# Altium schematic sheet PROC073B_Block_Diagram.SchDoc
size 431 x 279 mm; Date: Not shown in title block; ApprovedBy: Not shown in title block; CheckedBy: Not shown in title block; Author: Not shown in title block; CompanyName: Not shown in title block; Engineer: Not shown in title block; Organization: Not shown in title block; Address1: Not shown in title block; Address2: Not shown in title block; Address3: Not shown in title block; Address4: Not shown in title block; DocumentNumber: 1; Revision: Use project parameter SCH_Rev; SheetNumber: 1; SheetTotal: 9; PageSetup: Record=PageOptions¦CenterHorizontal=True¦CenterVertical=True¦PrintScale=1.00¦XCorrection=1.00¦YCorrection=1.00¦PrintKind=0¦BorderSize=5000000¦LeftOffset=0¦BottomOffset=0¦Orientation=2¦PaperLength=1000¦PaperWidth=1000¦Scale=100¦PaperSource=15¦PrintQuality=600¦MediaType=1¦DitherType=10¦PaperKind=Letter¦PrintScaleMode=1
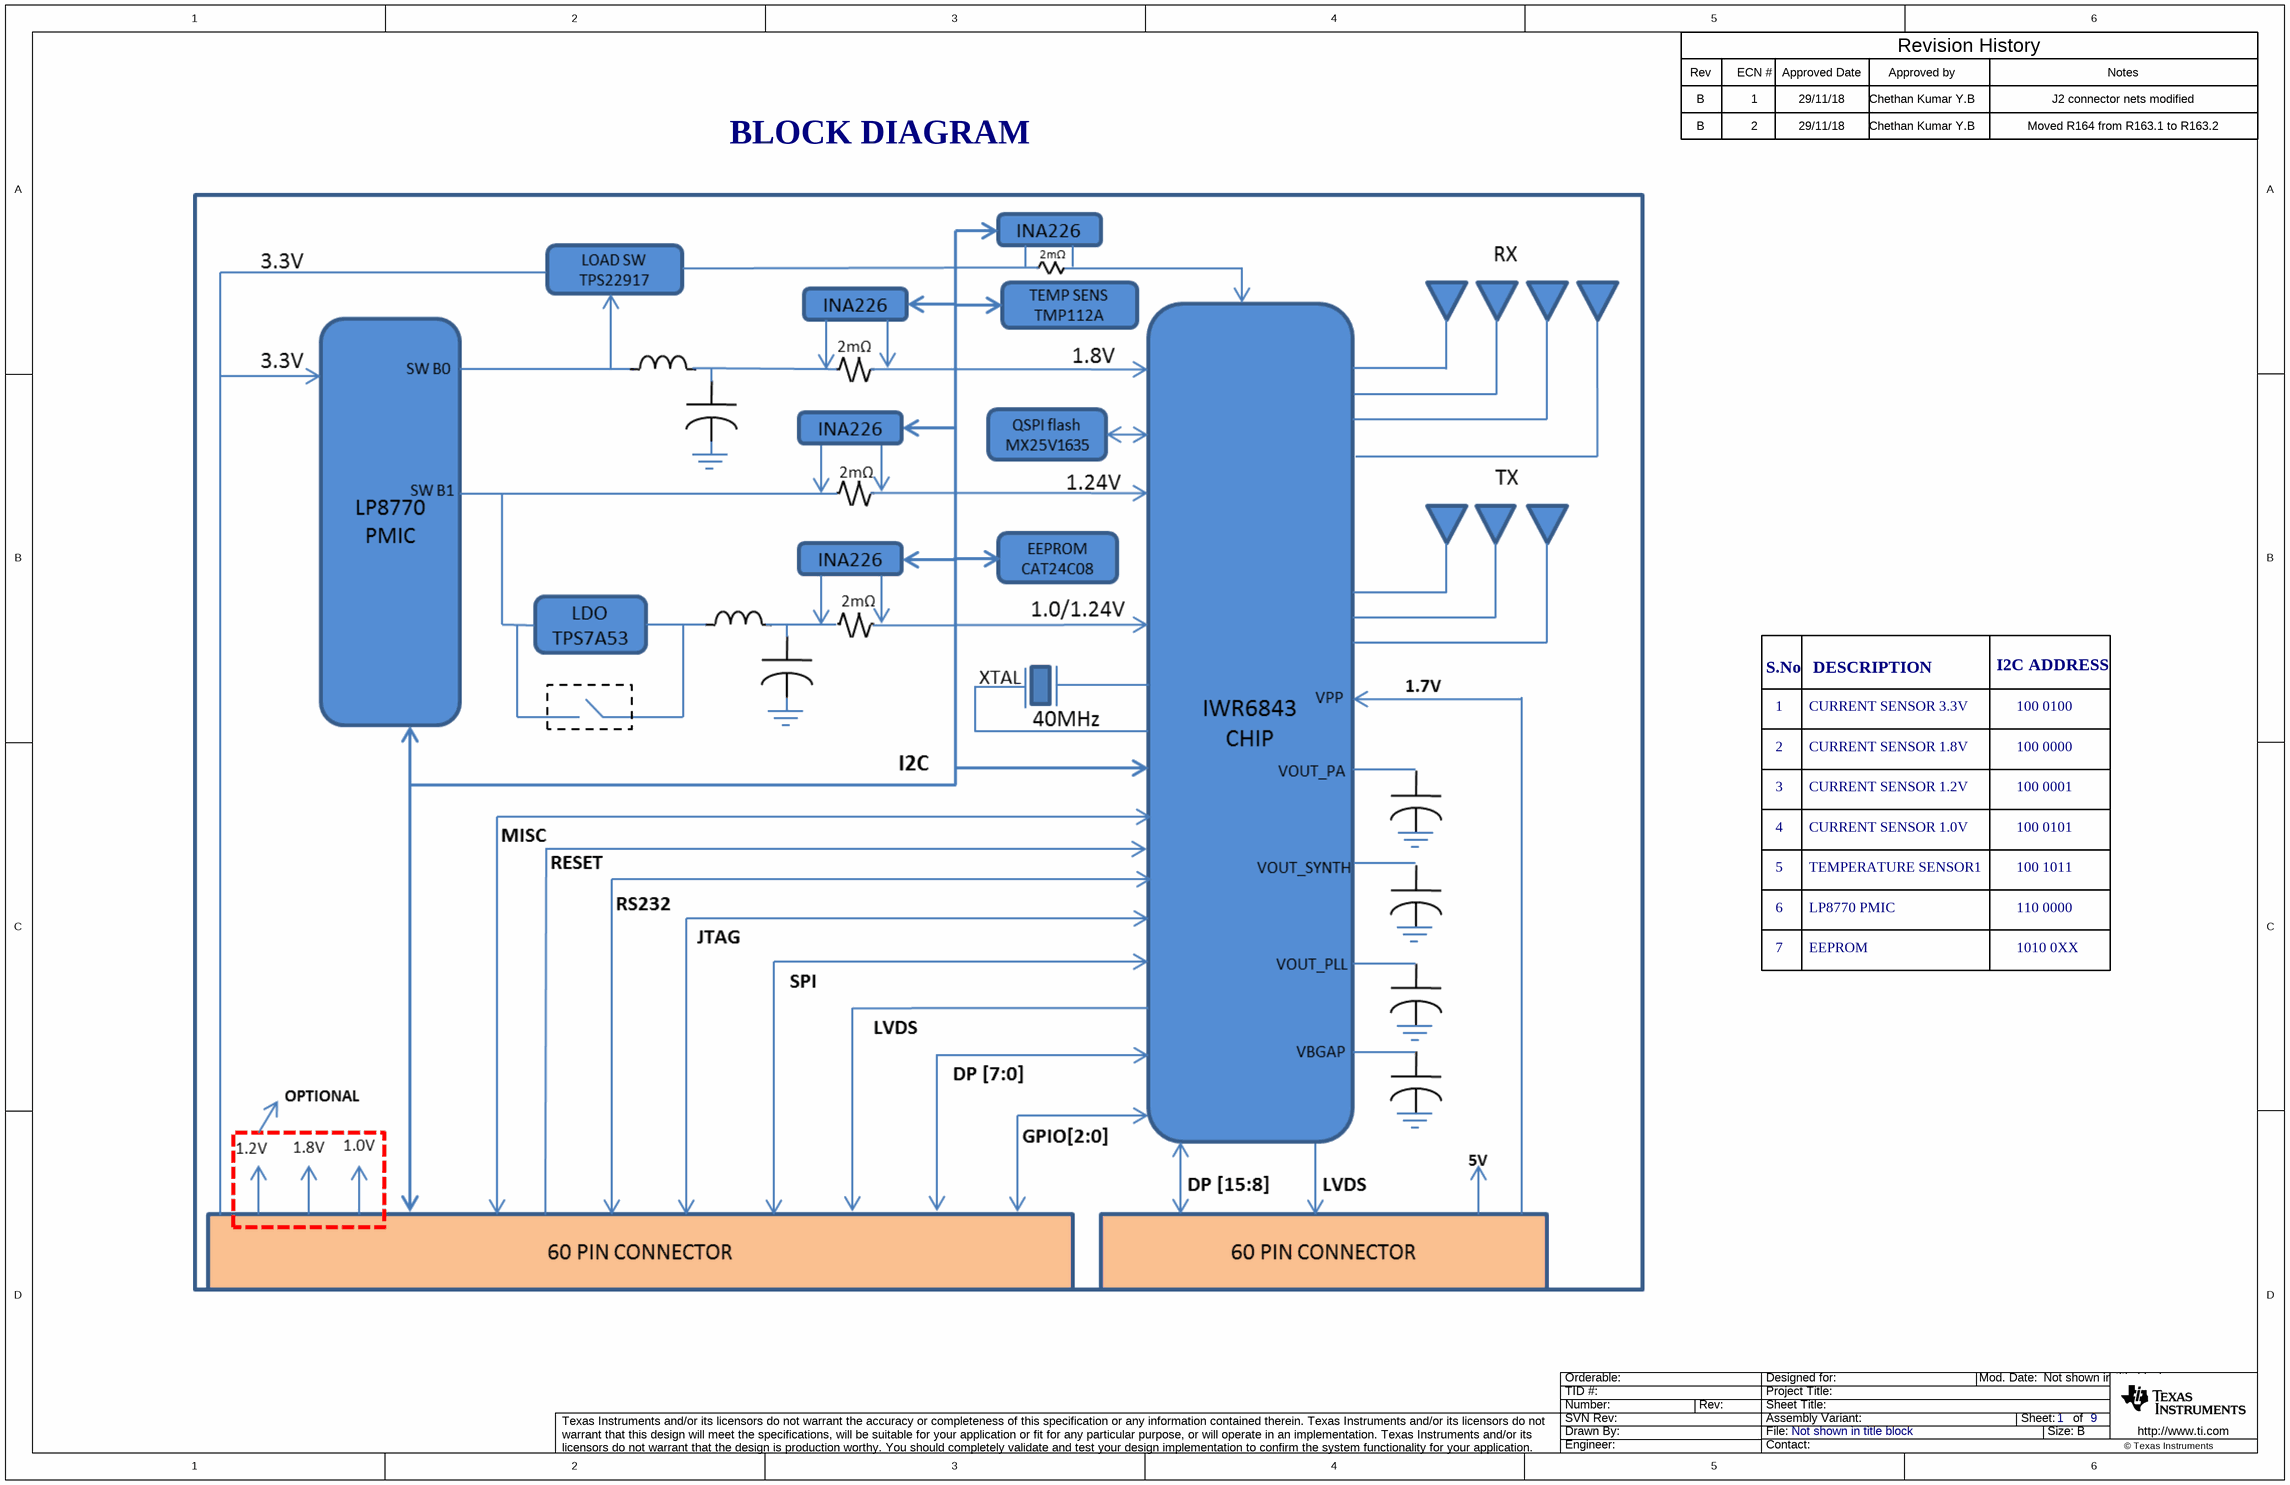
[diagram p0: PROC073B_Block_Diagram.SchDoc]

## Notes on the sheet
- Rev
- B
- ECN #
- 1
- Approved Date
- 29/11/18
- Approved by
- Chethan Kumar Y.B
- Revision History
- Notes
- J2 connector nets modified
- BLOCK DIAGRAM
- 2
- Moved R164 from R163.1 to R163.2
- S.No
- DESCRIPTION
- I2C ADDRESS
- CURRENT SENSOR 3.3V
- CURRENT SENSOR 1.8V
- 100 0100
- 100 0000
- 3
- 4
- CURRENT SENSOR 1.2V
- CURRENT SENSOR 1.0V
- 100 0001
- 100 0101
- 5
- TEMPERATURE SENSOR1
- 100 1011
- 6
- 7
- LP8770 PMIC
- EEPROM
- 1010 0XX
- 110 0000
